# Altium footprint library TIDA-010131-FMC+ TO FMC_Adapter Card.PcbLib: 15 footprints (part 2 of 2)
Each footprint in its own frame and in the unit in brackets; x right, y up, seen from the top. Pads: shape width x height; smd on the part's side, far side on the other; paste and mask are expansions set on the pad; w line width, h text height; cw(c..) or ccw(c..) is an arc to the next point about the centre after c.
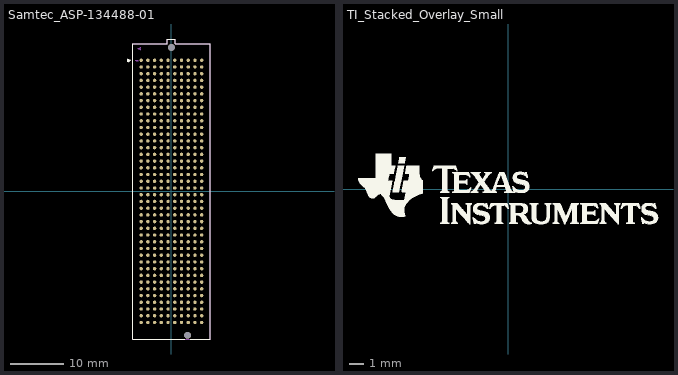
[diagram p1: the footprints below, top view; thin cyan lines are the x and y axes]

## Samtec_ASP-134488-01 [mm] "Connector, 1.27mm, 40x10, SMT"
height 7.24
pads (402):
  round 0.64 smd paste+0.125: A1(-5.715,24.765) A2(-5.715,23.495) A3(-5.715,22.225) A4(-5.715,20.955) A5(-5.715,19.685) A6(-5.715,18.415) A7(-5.715,17.145) A8(-5.715,15.875) A9(-5.715,14.605) A10(-5.715,13.335) A11(-5.715,12.065) A12(-5.715,10.795) A13(-5.715,9.525) A14(-5.715,8.255) A15(-5.715,6.985) A16(-5.715,5.715) A17(-5.715,4.445) A18(-5.715,3.175) A19(-5.715,1.905) A20(-5.715,0.635) A21(-5.715,-0.635) A22(-5.715,-1.905) A23(-5.715,-3.175) A24(-5.715,-4.445) A25(-5.715,-5.715) A26(-5.715,-6.985) A27(-5.715,-8.255) A28(-5.715,-9.525) A29(-5.715,-10.795) A30(-5.715,-12.065) A31(-5.715,-13.335) A32(-5.715,-14.605) A33(-5.715,-15.875) A34(-5.715,-17.145) A35(-5.715,-18.415) A36(-5.715,-19.685) A37(-5.715,-20.955) A38(-5.715,-22.225) A39(-5.715,-23.495) A40(-5.715,-24.765) B1(-4.445,24.765) B2(-4.445,23.495) B3(-4.445,22.225) B4(-4.445,20.955) B5(-4.445,19.685) B6(-4.445,18.415) B7(-4.445,17.145) B8(-4.445,15.875) B9(-4.445,14.605) B10(-4.445,13.335) B11(-4.445,12.065) B12(-4.445,10.795) B13(-4.445,9.525) B14(-4.445,8.255) B15(-4.445,6.985) B16(-4.445,5.715) B17(-4.445,4.445) B18(-4.445,3.175) B19(-4.445,1.905) B20(-4.445,0.635) B21(-4.445,-0.635) B22(-4.445,-1.905) B23(-4.445,-3.175) B24(-4.445,-4.445) B25(-4.445,-5.715) B26(-4.445,-6.985) B27(-4.445,-8.255) B28(-4.445,-9.525) B29(-4.445,-10.795) B30(-4.445,-12.065) B31(-4.445,-13.335) B32(-4.445,-14.605) B33(-4.445,-15.875) B34(-4.445,-17.145) B35(-4.445,-18.415) B36(-4.445,-19.685) B37(-4.445,-20.955) B38(-4.445,-22.225) B39(-4.445,-23.495) B40(-4.445,-24.765) C1(-3.175,24.765) C2(-3.175,23.495) C3(-3.175,22.225) C4(-3.175,20.955) C5(-3.175,19.685) C6(-3.175,18.415) C7(-3.175,17.145) C8(-3.175,15.875) C9(-3.175,14.605) C10(-3.175,13.335) C11(-3.175,12.065) C12(-3.175,10.795) C13(-3.175,9.525) C14(-3.175,8.255) C15(-3.175,6.985) C16(-3.175,5.715) C17(-3.175,4.445) C18(-3.175,3.175) C19(-3.175,1.905) C20(-3.175,0.635) C21(-3.175,-0.635) C22(-3.175,-1.905) C23(-3.175,-3.175) C24(-3.175,-4.445) C25(-3.175,-5.715) C26(-3.175,-6.985) C27(-3.175,-8.255) C28(-3.175,-9.525) C29(-3.175,-10.795) C30(-3.175,-12.065) C31(-3.175,-13.335) C32(-3.175,-14.605) C33(-3.175,-15.875) C34(-3.175,-17.145) C35(-3.175,-18.415) C36(-3.175,-19.685) C37(-3.175,-20.955) C38(-3.175,-22.225) C39(-3.175,-23.495) C40(-3.175,-24.765) D1(-1.905,24.765) D2(-1.905,23.495) D3(-1.905,22.225) D4(-1.905,20.955) D5(-1.905,19.685) D6(-1.905,18.415) D7(-1.905,17.145) D8(-1.905,15.875) D9(-1.905,14.605) D10(-1.905,13.335) D11(-1.905,12.065) D12(-1.905,10.795) D13(-1.905,9.525) D14(-1.905,8.255) D15(-1.905,6.985) D16(-1.905,5.715) D17(-1.905,4.445) D18(-1.905,3.175) D19(-1.905,1.905) D20(-1.905,0.635) D21(-1.905,-0.635) D22(-1.905,-1.905) D23(-1.905,-3.175) D24(-1.905,-4.445) D25(-1.905,-5.715) D26(-1.905,-6.985) D27(-1.905,-8.255) D28(-1.905,-9.525) D29(-1.905,-10.795) D30(-1.905,-12.065) D31(-1.905,-13.335) D32(-1.905,-14.605) D33(-1.905,-15.875) D34(-1.905,-17.145) D35(-1.905,-18.415) D36(-1.905,-19.685) D37(-1.905,-20.955) D38(-1.905,-22.225) D39(-1.905,-23.495) D40(-1.905,-24.765) E1(-0.635,24.765) E2(-0.635,23.495) E3(-0.635,22.225) E4(-0.635,20.955) E5(-0.635,19.685) E6(-0.635,18.415) E7(-0.635,17.145) E8(-0.635,15.875) E9(-0.635,14.605) E10(-0.635,13.335) E11(-0.635,12.065) E12(-0.635,10.795) E13(-0.635,9.525) E14(-0.635,8.255) E15(-0.635,6.985) E16(-0.635,5.715) E17(-0.635,4.445) E18(-0.635,3.175) E19(-0.635,1.905) E20(-0.635,0.635) E21(-0.635,-0.635) E22(-0.635,-1.905) E23(-0.635,-3.175) E24(-0.635,-4.445) E25(-0.635,-5.715) E26(-0.635,-6.985) E27(-0.635,-8.255) E28(-0.635,-9.525) E29(-0.635,-10.795) E30(-0.635,-12.065) E31(-0.635,-13.335) E32(-0.635,-14.605) E33(-0.635,-15.875) E34(-0.635,-17.145) E35(-0.635,-18.415) E36(-0.635,-19.685) E37(-0.635,-20.955) E38(-0.635,-22.225) E39(-0.635,-23.495) E40(-0.635,-24.765) F1(0.635,24.765) F2(0.635,23.495) F3(0.635,22.225) F4(0.635,20.955) F5(0.635,19.685) F6(0.635,18.415) F7(0.635,17.145) F8(0.635,15.875) F9(0.635,14.605) F10(0.635,13.335) F11(0.635,12.065) F12(0.635,10.795) F13(0.635,9.525) F14(0.635,8.255) F15(0.635,6.985) F16(0.635,5.715) F17(0.635,4.445) F18(0.635,3.175) F19(0.635,1.905) F20(0.635,0.635) F21(0.635,-0.635) F22(0.635,-1.905) F23(0.635,-3.175) F24(0.635,-4.445) F25(0.635,-5.715) F26(0.635,-6.985) F27(0.635,-8.255) F28(0.635,-9.525) F29(0.635,-10.795) F30(0.635,-12.065) F31(0.635,-13.335) F32(0.635,-14.605) F33(0.635,-15.875) F34(0.635,-17.145) F35(0.635,-18.415) F36(0.635,-19.685) F37(0.635,-20.955) F38(0.635,-22.225) F39(0.635,-23.495) F40(0.635,-24.765) G1(1.905,24.765) G2(1.905,23.495) G3(1.905,22.225) G4(1.905,20.955) G5(1.905,19.685) G6(1.905,18.415) G7(1.905,17.145) G8(1.905,15.875) G9(1.905,14.605) G10(1.905,13.335) G11(1.905,12.065) G12(1.905,10.795) G13(1.905,9.525) G14(1.905,8.255) G15(1.905,6.985) G16(1.905,5.715) G17(1.905,4.445) G18(1.905,3.175) G19(1.905,1.905) G20(1.905,0.635) G21(1.905,-0.635) G22(1.905,-1.905) G23(1.905,-3.175) G24(1.905,-4.445) G25(1.905,-5.715) G26(1.905,-6.985) G27(1.905,-8.255) G28(1.905,-9.525) G29(1.905,-10.795) G30(1.905,-12.065) G31(1.905,-13.335) G32(1.905,-14.605) G33(1.905,-15.875) G34(1.905,-17.145) G35(1.905,-18.415) G36(1.905,-19.685) G37(1.905,-20.955) G38(1.905,-22.225) G39(1.905,-23.495) G40(1.905,-24.765) H1(3.175,24.765) H2(3.175,23.495) H3(3.175,22.225) H4(3.175,20.955) H5(3.175,19.685) H6(3.175,18.415) H7(3.175,17.145) H8(3.175,15.875) H9(3.175,14.605) H10(3.175,13.335) H11(3.175,12.065) H12(3.175,10.795) H13(3.175,9.525) H14(3.175,8.255) H15(3.175,6.985) H16(3.175,5.715) H17(3.175,4.445) H18(3.175,3.175) H19(3.175,1.905) H20(3.175,0.635) H21(3.175,-0.635) H22(3.175,-1.905) H23(3.175,-3.175) H24(3.175,-4.445) H25(3.175,-5.715) H26(3.175,-6.985) H27(3.175,-8.255) H28(3.175,-9.525) H29(3.175,-10.795) H30(3.175,-12.065) H31(3.175,-13.335) H32(3.175,-14.605) H33(3.175,-15.875) H34(3.175,-17.145) H35(3.175,-18.415) H36(3.175,-19.685) H37(3.175,-20.955) H38(3.175,-22.225) H39(3.175,-23.495) H40(3.175,-24.765) J1(4.445,24.765) J2(4.445,23.495) J3(4.445,22.225) J4(4.445,20.955) J5(4.445,19.685) J6(4.445,18.415) J7(4.445,17.145) J8(4.445,15.875) J9(4.445,14.605) J10(4.445,13.335) J11(4.445,12.065) J12(4.445,10.795) J13(4.445,9.525) J14(4.445,8.255) J15(4.445,6.985) J16(4.445,5.715) J17(4.445,4.445) J18(4.445,3.175) J19(4.445,1.905) J20(4.445,0.635) J21(4.445,-0.635) J22(4.445,-1.905) J23(4.445,-3.175) J24(4.445,-4.445) J25(4.445,-5.715) J26(4.445,-6.985) J27(4.445,-8.255) J28(4.445,-9.525) J29(4.445,-10.795) J30(4.445,-12.065) J31(4.445,-13.335) J32(4.445,-14.605) J33(4.445,-15.875) J34(4.445,-17.145) J35(4.445,-18.415) J36(4.445,-19.685) J37(4.445,-20.955) J38(4.445,-22.225) J39(4.445,-23.495) J40(4.445,-24.765) K1(5.715,24.765) K2(5.715,23.495) K3(5.715,22.225) K4(5.715,20.955) K5(5.715,19.685) K6(5.715,18.415) K7(5.715,17.145) K8(5.715,15.875) K9(5.715,14.605) K10(5.715,13.335) K11(5.715,12.065) K12(5.715,10.795) K13(5.715,9.525) K14(5.715,8.255) K15(5.715,6.985) K16(5.715,5.715) K17(5.715,4.445) K18(5.715,3.175) K19(5.715,1.905) K20(5.715,0.635) K21(5.715,-0.635) K22(5.715,-1.905) K23(5.715,-3.175) K24(5.715,-4.445) K25(5.715,-5.715) K26(5.715,-6.985) K27(5.715,-8.255) K28(5.715,-9.525) K29(5.715,-10.795) K30(5.715,-12.065) K31(5.715,-13.335) K32(5.715,-14.605) K33(5.715,-15.875) K34(5.715,-17.145) K35(5.715,-18.415) K36(5.715,-19.685) K37(5.715,-20.955) K38(5.715,-22.225) K39(5.715,-23.495) K40(5.715,-24.765)
  round 1.27 hole 1.27 unplated mask+0: MH1(0,27.19) MH2(3.05,-27.19)
Top Overlay:
  lines w0.2: 2.5,-27.89 -7.34,-27.89 -7.34,27.89 -0.76,27.89 -0.76,28.78 0.76,28.78 0.76,27.89 7.34,27.89 7.34,-27.89 3.6,-27.89
  lines w0.254: -8.25,24.5 -8.25,25 -7.75,24.75 -8.25,24.5
Mechanical 5:
  drawing of 333 lines, arcs and shapes, not listed
3D body "ASP-134488-01.stp": height 7.11, standoff -1.27, extent -7.34,-27.89 7.34,28.78

## TI_Stacked_Overlay_Small [mil]
height 375.2
Top Overlay:
  drawing of 18 lines, arcs and shapes, not listed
